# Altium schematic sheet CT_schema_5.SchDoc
size 514 x 409 mm
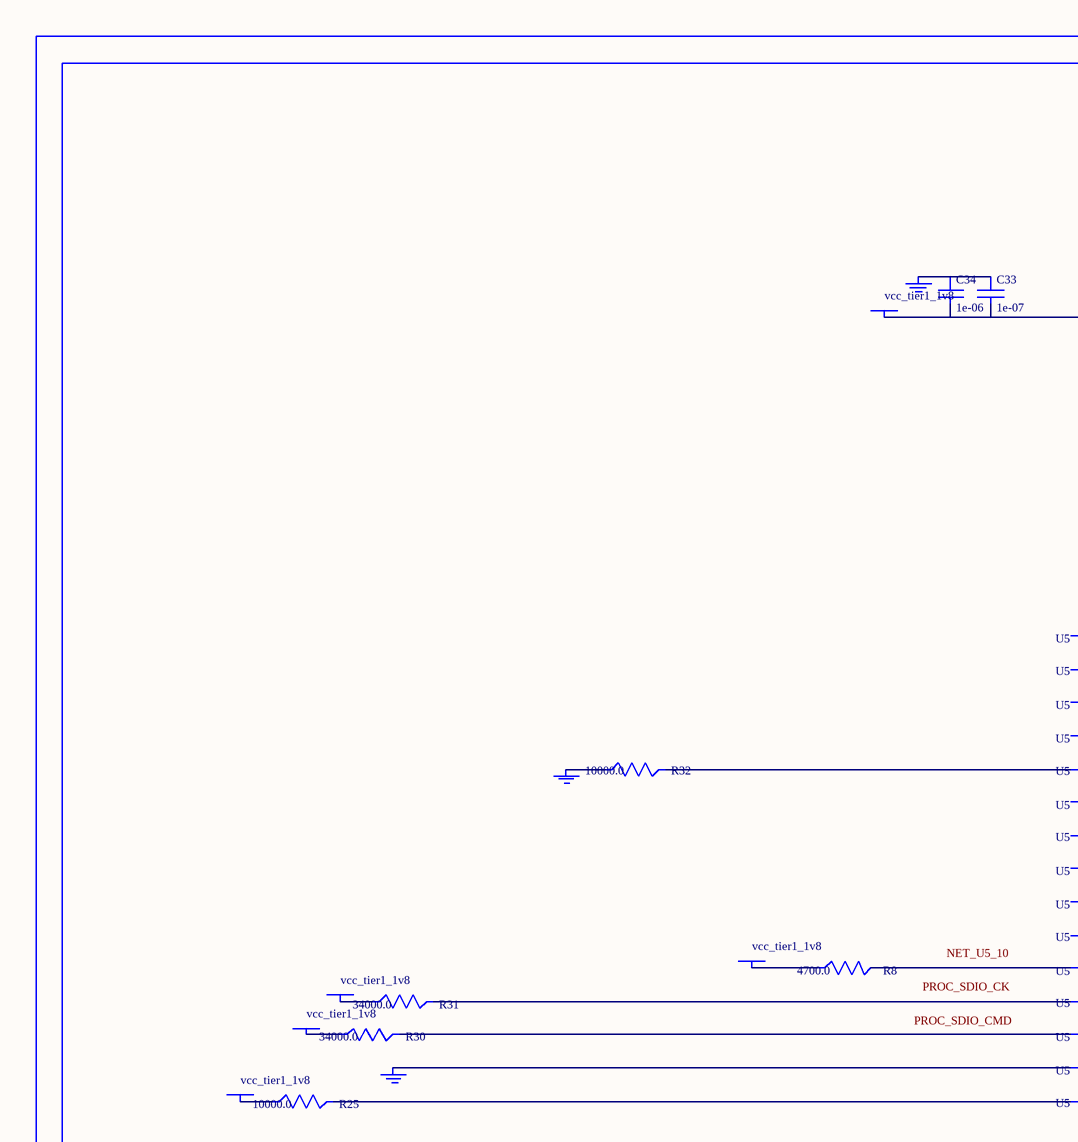
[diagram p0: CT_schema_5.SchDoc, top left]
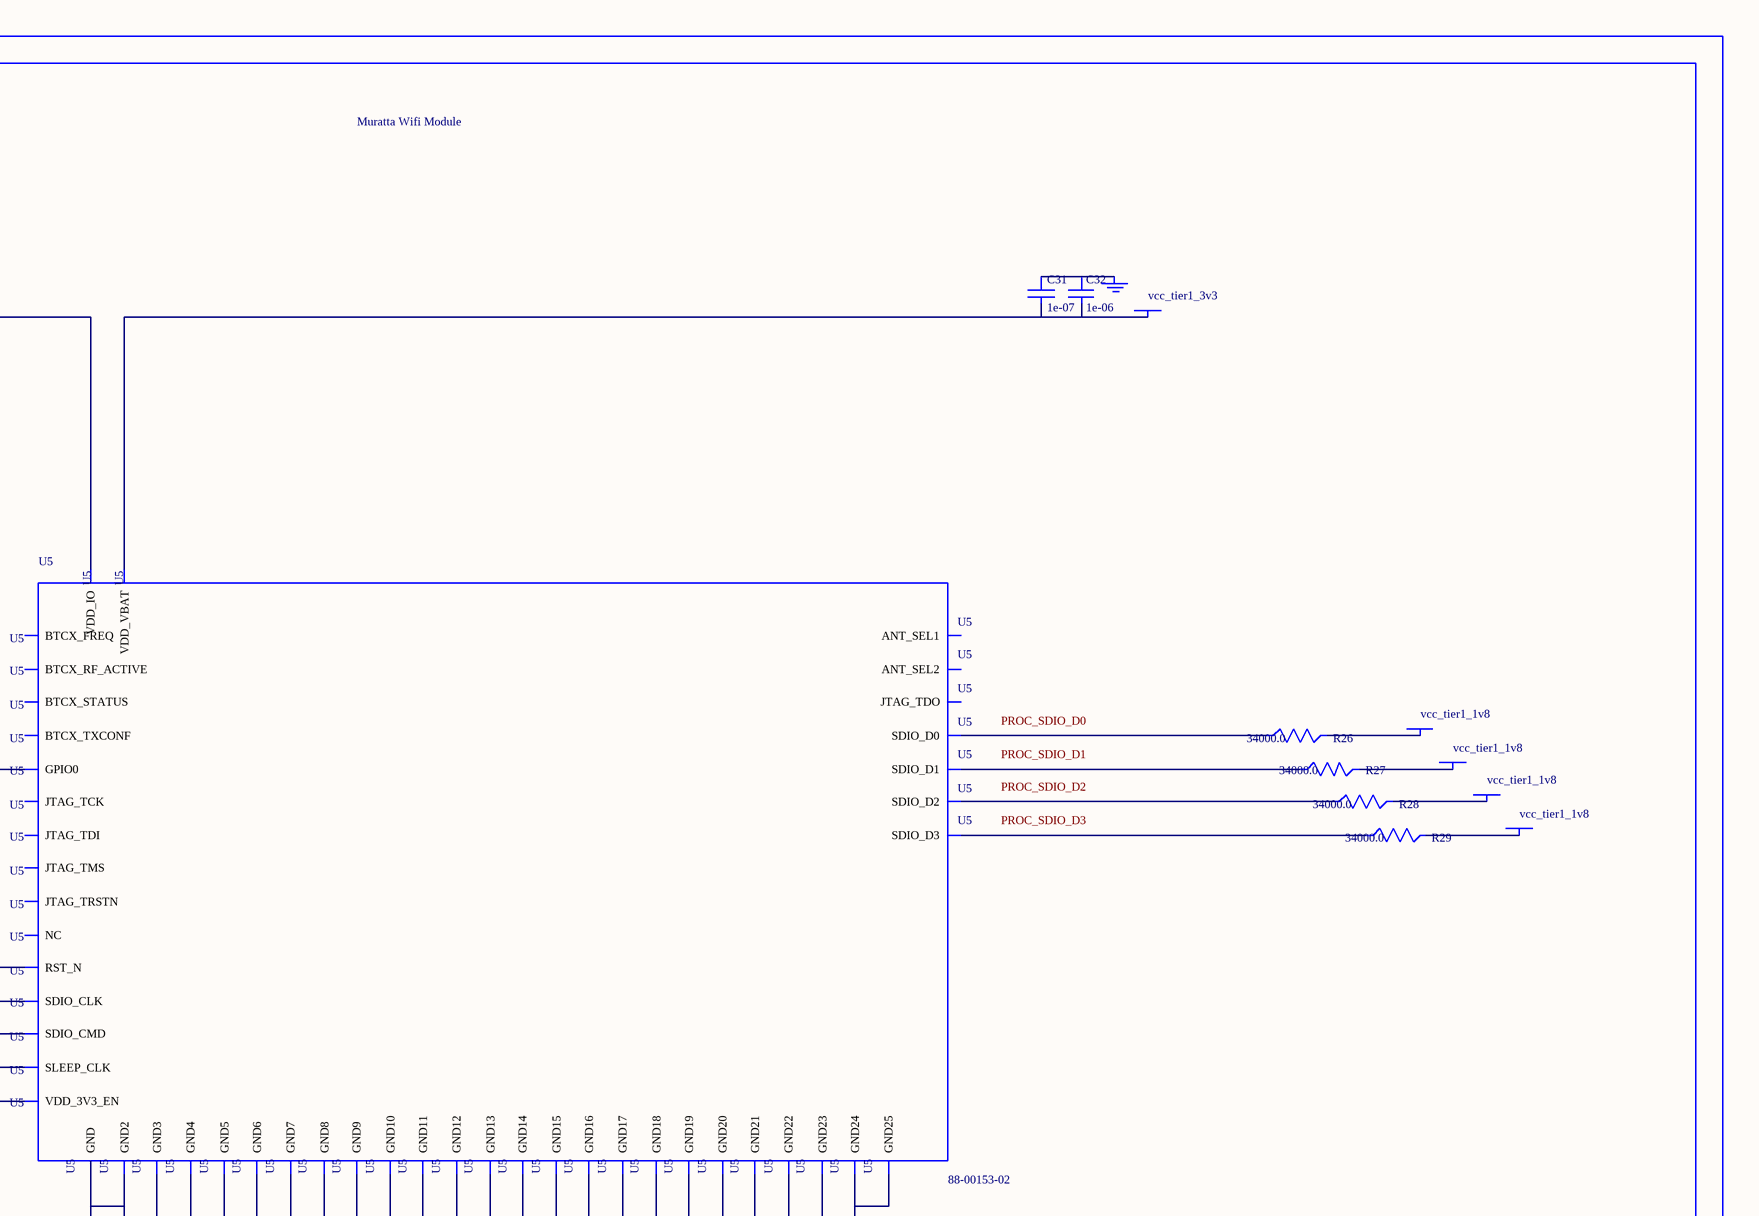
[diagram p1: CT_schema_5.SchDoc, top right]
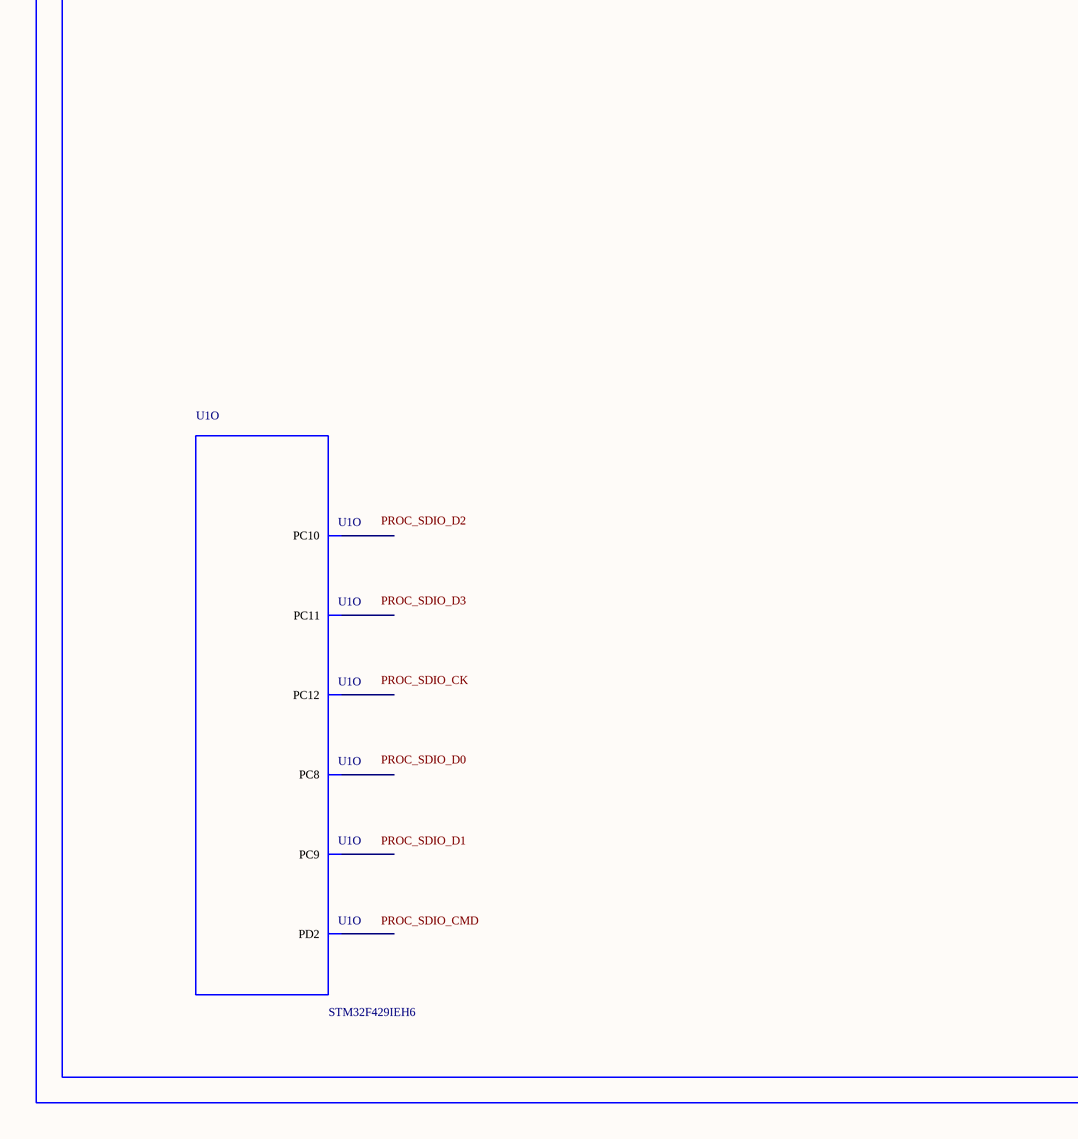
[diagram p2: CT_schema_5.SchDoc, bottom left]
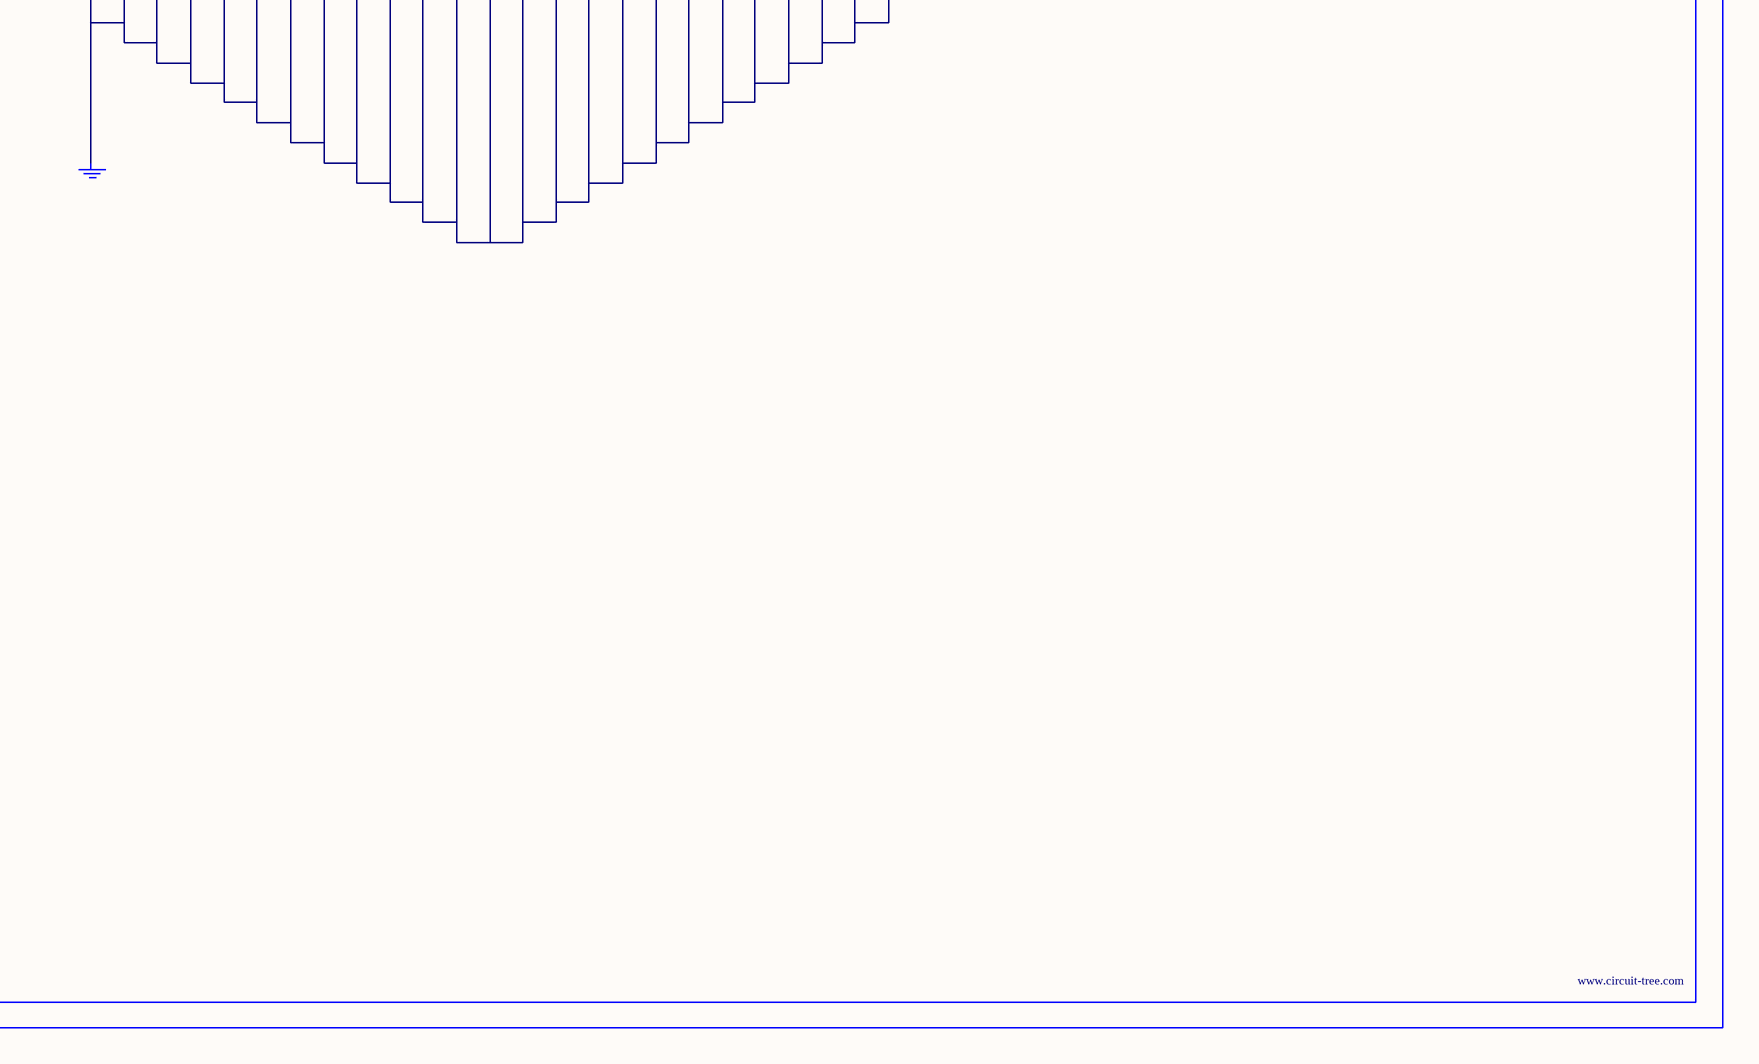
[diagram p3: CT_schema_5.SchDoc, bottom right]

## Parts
BORDER4  (no value)
C31  1e-07  [C0402]
C32  1e-06  [C0603]
C33  1e-07  [C0402]
C34  1e-06  [C0603]
GND_INSTANCE_4_0  (no value)
GND_INSTANCE_4_1  (no value)
GND_INSTANCE_4_2  (no value)
GND_INSTANCE_4_3  (no value)
GND_INSTANCE_4_4  (no value)
POWER_INSTANCE_4_0  vcc_tier1_1v8
POWER_INSTANCE_4_1  vcc_tier1_1v8
POWER_INSTANCE_4_2  vcc_tier1_3v3
POWER_INSTANCE_4_3  vcc_tier1_1v8
POWER_INSTANCE_4_4  vcc_tier1_1v8
POWER_INSTANCE_4_5  vcc_tier1_1v8
POWER_INSTANCE_4_6  vcc_tier1_1v8
POWER_INSTANCE_4_7  vcc_tier1_1v8
POWER_INSTANCE_4_8  vcc_tier1_1v8
POWER_INSTANCE_4_9  vcc_tier1_1v8
R8  4700.0  [R0603]
R25  10000.0  [R0603]
R26  34000.0  [R0603]
R27  34000.0  [R0603]
R28  34000.0  [R0603]
R29  34000.0  [R0603]
R30  34000.0  [R0603]
R31  34000.0  [R0603]
R32  10000.0  [R0603]
U1  STM32F429IEH6  [UFBGA176_25]  (part O of 15)
U5  88-00153-02  [88-00153-02]

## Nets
NetC31_1: C31.1 C32.1 GND_INSTANCE_4_1.0(GND)
NetC31_2: C31.2 C32.2 POWER_INSTANCE_4_2.0(PWR) U5.12(VDD_VBAT)
NetC33_1: C33.1 C34.1 GND_INSTANCE_4_3.0(GND)
NetC33_2: C33.2 C34.2 POWER_INSTANCE_4_3.0(PWR) U5.33(VDD_IO)
NetGND_INSTANCE_4_0_0: GND_INSTANCE_4_0.0(GND) R32.1
NetGND_INSTANCE_4_2_0: GND_INSTANCE_4_2.0(GND) U5.31(SLEEP_CLK)
NetGND_INSTANCE_4_4_0: GND_INSTANCE_4_4.0(GND) U5.1(GND) U5.9(GND2) U5.13(GND3) U5.14(GND4) U5.15(GND5) U5.16(GND6) U5.17(GND7) U5.18(GND8) U5.19(GND9) U5.20(GND10) U5.21(GND11) U5.22(GND12) U5.23(GND13) U5.24(GND14) U5.25(GND15) U5.26(GND16) U5.27(GND17) U5.32(GND18) U5.39(GND19) U5.40(GND20) U5.41(GND21) U5.42(GND22) U5.43(GND23) U5.44(GND24) U5.49(GND25)
NetPOWER_INSTANCE_4_0_0: POWER_INSTANCE_4_0.0(PWR) R28.2
NetPOWER_INSTANCE_4_1_0: POWER_INSTANCE_4_1.0(PWR) R25.1
NetPOWER_INSTANCE_4_4_0: POWER_INSTANCE_4_4.0(PWR) R27.2
NetPOWER_INSTANCE_4_5_0: POWER_INSTANCE_4_5.0(PWR) R26.2
NetPOWER_INSTANCE_4_6_0: POWER_INSTANCE_4_6.0(PWR) R31.1
NetPOWER_INSTANCE_4_7_0: POWER_INSTANCE_4_7.0(PWR) R30.1
NetPOWER_INSTANCE_4_8_0: POWER_INSTANCE_4_8.0(PWR) R29.2
NetPOWER_INSTANCE_4_9_0: POWER_INSTANCE_4_9.0(PWR) R8.1
NetR8_2: R8.2 U5.10(RST_N)
NetR25_2: R25.2 U5.11(VDD_3V3_EN)
NetR26_1: R26.1 U5.35(SDIO_D0)
NetR27_1: R27.1 U5.34(SDIO_D1)
NetR28_1: R28.1 U5.2(SDIO_D2)
NetR29_1: R29.1 U5.38(SDIO_D3)
NetR30_2: R30.2 U5.37(SDIO_CMD)
NetR31_2: R31.2 U5.36(SDIO_CLK)
NetR32_2: R32.2 U5.6(GPIO0)

Not connected (* = marked no-connect by the designer): U1 A12(PC12) B13(PC11) B14(PC10) D12(PD2) F14(PC9) G14(PC8); U5 3(JTAG_TDI) 4(JTAG_TDO) 5(BTCX_FREQ) 7(ANT_SEL2) 8(ANT_SEL1) 28(BTCX_STATUS) 29(BTCX_TXCONF) 30(BTCX_RF_ACTIVE) 45(JTAG_TCK) 46(JTAG_TRSTN) 47(JTAG_TMS) 48(NC)

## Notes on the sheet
- Labels drawn without touching a wire or pin: NET_U5_10, PROC_SDIO_CK, PROC_SDIO_CMD, PROC_SDIO_D0, PROC_SDIO_D1, PROC_SDIO_D2, PROC_SDIO_D3

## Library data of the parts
BORDER4 = BORDER_PAGE4
C31 C33 = C0402C104K3RACTU
C32 C34 = C0603C105K3RACTU
GND_INSTANCE_4_0-GND_INSTANCE_4_4 = GND
POWER_INSTANCE_4_0-POWER_INSTANCE_4_9 = PWR
R8 = RC0603JR-074K7L
R25 R32 = RC0603JR-0710KL
R26-R31 = ERA3ARB3402V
